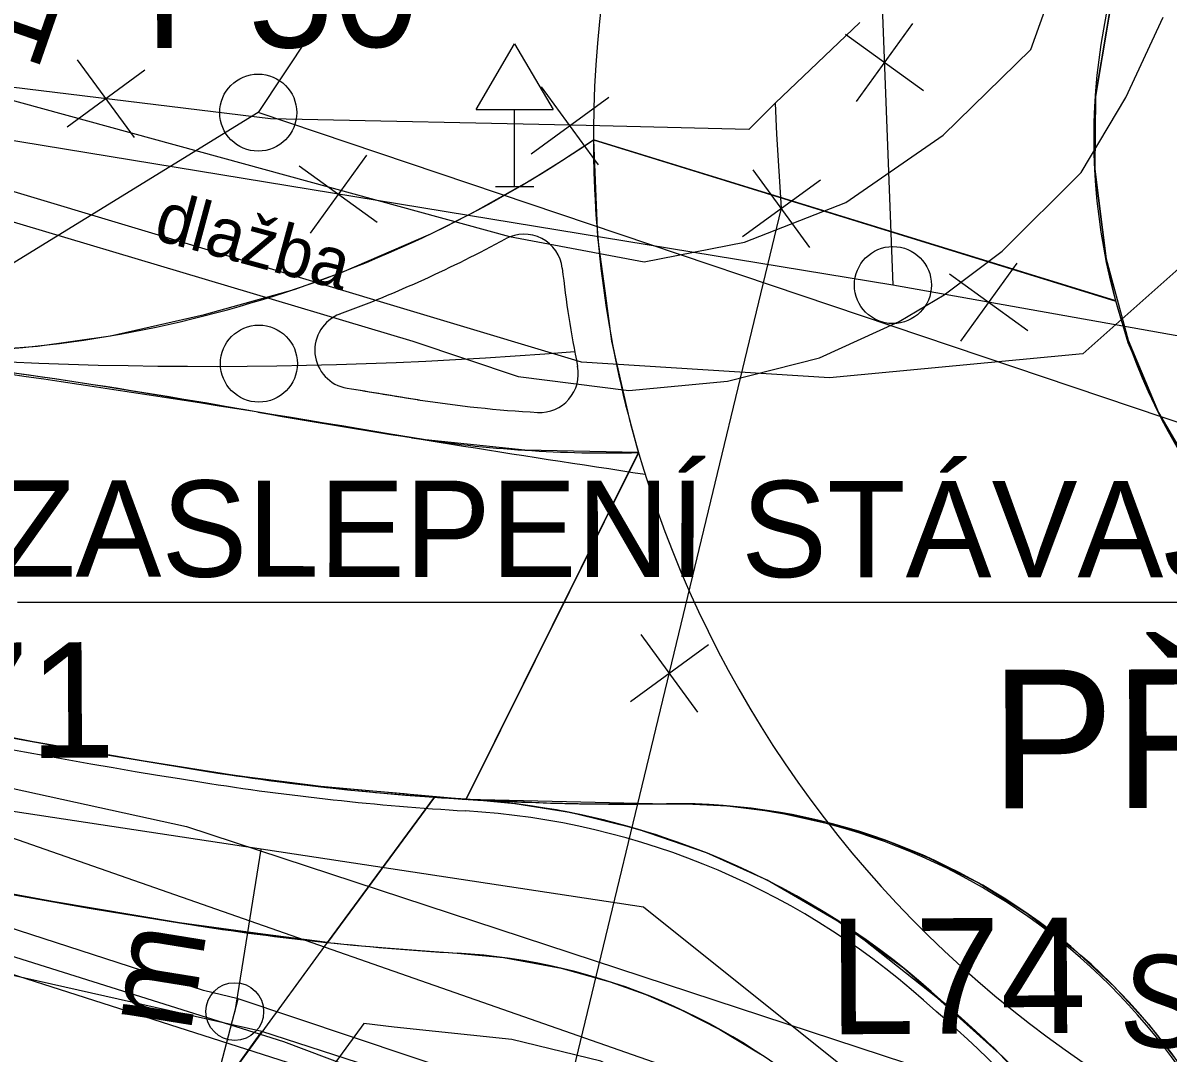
# Model space of a CAD drawing. Extents: x -643342 to -638635, y -1201752 to -1189948.
# Drawn here: x -639514.49 to -639499.63, y -1192725.54 to -1192712.17 of the extents above; entities that cross this region are included whole.
import ezdxf

# ---------------------------------------------------------------- set-up
doc = ezdxf.new("R2010")
doc.units = 0
for name, color, linetype in [('-zbytky_kruháče', 7, 'Continuous'), ('2', 7, 'Continuous'), ('IS_PLYN_STL', 7, 'Continuous'), ('IS_TELEF_MISTNI_ZAMERENO', 7, 'Continuous'), ('IS_VODOVOD_VAS', 7, 'Continuous'), ('K-HRANICE_KN', 7, 'Continuous'), ('kanalizace_dešťová_stávající', 7, 'Continuous'), ('N-CHODNIK', 7, 'Continuous'), ('N-KAN_DEST_SACHTY-NÁVRH', 7, 'Continuous'), ('N-KAN_DEST_TRASA-NÁVRH', 7, 'Continuous'), ('N-OBVOD STAVBY 06', 7, 'Continuous'), ('N-OSA', 7, 'Continuous'), ('N-rusene_vedeni', 7, 'Continuous'), ('N-SILNICE', 7, 'Continuous'), ('N-SRAFY_PLOCHY', 7, 'Continuous'), ('RWE_STL_PRIPOJKY', 7, 'Continuous'), ('RWE_STL_RADY', 7, 'Continuous'), ('tomaštík - Džuganovi - Vrstva 36', 7, 'Continuous'), ('Vrstva 46', 7, 'Continuous'), ('Z-hrany_a_čáry', 7, 'Continuous'), ('Z-popisy', 7, 'Continuous'), ('Z-značky', 7, 'Continuous'), ('Z-šachty_poklopy', 7, 'Continuous')]:
    doc.layers.add(name, color=color, linetype=linetype)

msp = doc.modelspace()

# ---------------------------------------------------------------- linework, layer by layer
at = {"layer": '-zbytky_kruháče'}
for centre, radius, start, end in [((-639492.588, -1192713.663), 14.5, 152.4602, 296.3322), ((-639516.023, -1192700.666), 15.789, 267.4282, 304.4652), ((-639526.387, -1192800.021), 84.137, 79.7689, 83.41017), ((-639465.318, -1192444.786), 276.313, 260.3906, 261.44619)]:
    msp.add_arc(centre, radius, start, end, dxfattribs=at)
at = {"layer": '2'}
msp.add_line((-639514.564, -1192719.686), (-639469.586, -1192719.686), dxfattribs=at)
msp.add_circle((-639511.743, -1192725.003), 0.375, dxfattribs=at)
at = {"layer": 'IS_PLYN_STL'}
for points in [[(-639501.39, -1192783.75), (-639500.989, -1192780.093), (-639500.16, -1192772.52), (-639499.45, -1192766.45), (-639499.2, -1192762.17), (-639498.55, -1192754.89), (-639497.68, -1192743.88), (-639497.18, -1192733.61), (-639497.87, -1192731.06), (-639499.7, -1192729.08), (-639500.91, -1192728.3), (-639501.94, -1192727.99), (-639507.97, -1192726.09), (-639511.7, -1192724.84), (-639512.15, -1192724.73), (-639515.02, -1192723.8), (-639520.31, -1192722.34), (-639520.46, -1192722.3), (-639520.92, -1192722.11)], [(-639512.5, -1192727.91), (-639512.25, -1192726.94), (-639511.7, -1192724.84)]]:
    msp.add_lwpolyline(points, dxfattribs=at)
at = {"layer": 'IS_TELEF_MISTNI_ZAMERENO'}
for p, q in [((-639503.63, -1192712.16), (-639504.73, -1192713.21)), ((-639511.28, -1192713.41), (-639515.55, -1192712.89)), ((-639504.73, -1192713.21), (-639505.07, -1192713.55)), ((-639504.73, -1192713.21), (-639504.71, -1192713.61)), ((-639507.18, -1192713.5), (-639511.28, -1192713.41)), ((-639505.07, -1192713.55), (-639507.18, -1192713.5)), ((-639504.71, -1192713.61), (-639504.65, -1192714.57)), ((-639504.65, -1192714.57), (-639507.56, -1192726.64)), ((-639504.65, -1192714.57), (-639507.56, -1192726.64)), ((-639515, -1192724.17), (-639511.11, -1192725.39)), ((-639515, -1192724.17), (-639511.11, -1192725.39)), ((-639511.11, -1192725.39), (-639509.95, -1192725.83))]:
    msp.add_line(p, q, dxfattribs=at)
at = {"layer": 'IS_VODOVOD_VAS'}
msp.add_lwpolyline([(-639496.09, -1192729.96), (-639496.274, -1192729.942), (-639497.14, -1192730.02), (-639497.319, -1192730.013), (-639497.98, -1192729.852), (-639517.2, -1192723.7), (-639533.16, -1192716.44), (-639534.26, -1192716.19), (-639547.57, -1192711.28), (-639564.69, -1192707.49), (-639577.32, -1192705.32), (-639579.08, -1192705.18), (-639581.13, -1192706.12), (-639584.92, -1192706.29)], dxfattribs=at)
at = {"layer": 'K-HRANICE_KN'}
for p, q in [((-639507.244, -1192716.571), (-639522.497, -1192711.992)), ((-639507.244, -1192716.571), (-639522.497, -1192711.992)), ((-639499.172, -1192715.073), (-639500.733, -1192716.465)), ((-639499.172, -1192715.073), (-639500.733, -1192716.465)), ((-639500.733, -1192716.465), (-639504.024, -1192716.775)), ((-639500.733, -1192716.465), (-639504.024, -1192716.775)), ((-639504.024, -1192716.775), (-639507.244, -1192716.571)), ((-639504.024, -1192716.775), (-639507.244, -1192716.571)), ((-639514.8, -1192722.07), (-639512.37, -1192722.6)), ((-639512.37, -1192722.6), (-639501.84, -1192726.06))]:
    msp.add_line(p, q, dxfattribs=at)
at = {"layer": 'kanalizace_dešťová_stávající'}
for p, q in [((-639504.48, -1192681.98), (-639503.2, -1192715.57)), ((-639503.2, -1192715.57), (-639578.69, -1192703.18)), ((-639487.73, -1192718.33), (-639503.2, -1192715.57))]:
    msp.add_line(p, q, dxfattribs=at)
at = {"layer": 'N-CHODNIK'}
msp.add_lwpolyline([(-639519.358, -1192722.513), (-639519.9, -1192724.87), (-639515.62, -1192725.85), (-639512.469, -1192726.756), (-639510.539, -1192724.105), (-639511.377, -1192723.998), (-639512.461, -1192723.852), (-639514.111, -1192723.576), (-639515.895, -1192723.247), (-639517.764, -1192722.866)], close=True, dxfattribs=at)
at = {"layer": 'N-KAN_DEST_SACHTY-NÁVRH'}
msp.add_circle((-639511.439, -1192713.331), 0.5, dxfattribs=at)
at = {"layer": 'N-KAN_DEST_TRASA-NÁVRH'}
for points in [[(-639583.962, -1192528.01), (-639550.452, -1192564.184), (-639529.583, -1192588.026), (-639514.491, -1192612.048), (-639507.737, -1192644.326), (-639498.832, -1192694.254), (-639511.439, -1192713.331), (-639516.613, -1192716.507), (-639553.938, -1192703.739), (-639570.485, -1192701.616), (-639578.687, -1192703.18)], [(-639355.755, -1192712.633), (-639405.298, -1192719.503), (-639444.905, -1192722.803), (-639490.998, -1192720.223), (-639511.439, -1192713.331)]]:
    msp.add_lwpolyline(points, dxfattribs=at)
at = {"layer": 'N-OBVOD STAVBY 06'}
for points in [[(-639510.069, -1192725.158), (-639511.446, -1192727.05), (-639512.469, -1192726.756), (-639515.316, -1192725.938), (-639515.62, -1192725.85), (-639519.9, -1192724.87), (-639520.863, -1192724.597), (-639520.555, -1192723.257)], [(-639502.579, -1192729.232), (-639503.805, -1192727.835), (-639505.37, -1192726.464), (-639506.99, -1192725.648), (-639508.145, -1192725.368), (-639509.676, -1192725.206), (-639510.069, -1192725.158)]]:
    msp.add_lwpolyline(points, dxfattribs=at)
at = {"layer": 'N-OSA'}
msp.add_arc((-639512.074, -1192658.483), 58.143, 250.31441, 274.68016, dxfattribs=at)
at = {"layer": 'N-rusene_vedeni'}
for p, q in [((-639502.944, -1192712.172), (-639503.676, -1192713.186)), ((-639503.817, -1192712.313), (-639502.803, -1192713.045)), ((-639512.91, -1192712.781), (-639513.92, -1192713.519)), ((-639513.046, -1192713.655), (-639513.784, -1192712.645)), ((-639507.023, -1192714.007), (-639507.76, -1192712.998)), ((-639506.887, -1192713.134), (-639507.896, -1192713.871)), ((-639510.034, -1192713.882), (-639510.765, -1192714.895)), ((-639510.906, -1192714.023), (-639509.893, -1192714.754)), ((-639504.276, -1192715.082), (-639505.014, -1192714.072)), ((-639504.14, -1192714.208), (-639505.15, -1192714.946)), ((-639501.591, -1192715.285), (-639502.322, -1192716.299)), ((-639502.463, -1192715.426), (-639501.45, -1192716.158)), ((-639505.731, -1192721.117), (-639506.469, -1192720.107)), ((-639505.595, -1192720.243), (-639506.605, -1192720.981))]:
    msp.add_line(p, q, dxfattribs=at)
at = {"layer": 'N-SILNICE'}
msp.add_line((-639510.539, -1192724.105), (-639509.151, -1192722.22), dxfattribs=at)
msp.add_circle((-639492.588, -1192713.663), 8, dxfattribs=at)
for centre, radius, start, end in [((-639516.023, -1192700.666), 16.289, 290.2787, 298.5882), ((-639507.989, -1192715.409), 0.5, 6.4672, 118.5882), ((-639492.588, -1192713.663), 15, 186.4672, 191.391), ((-639510.204, -1192716.415), 0.5, 110.2787, 260.6168), ((-639507.783, -1192716.724), 0.5, 266.7338, 11.391), ((-639453.766, -1192373.81), 347.722, 260.6455, 260.80232), ((-639506.892, -1192701.125), 16.125, 261.1699, 266.7338), ((-639496.485, -1192623.111), 100, 250.31486, 260.98854), ((-639496.485, -1192623.111), 100.15, 250.31486, 260.98854), ((-639506.892, -1192701.125), 16.625, 261.1699, 271.3474), ((-639496.485, -1192623.111), 102, 250.31486, 260.98854), ((-639506.666, -1192687.309), 35, 260.9885, 270.8671), ((-639506.666, -1192687.309), 35, 260.9885, 266.6063), ((-639506.666, -1192687.309), 35.15, 260.9885, 266.6063), ((-639509.33, -1192732.23), 10, 47.2487, 86.6063), ((-639509.33, -1192732.23), 9.85, 47.2487, 86.6063), ((-639506.015, -1192730.304), 8, 9.4731, 90.8671), ((-639506.666, -1192687.309), 37, 260.9885, 266.6063), ((-639509.33, -1192732.23), 8, 47.2487, 86.6063), ((-639512.285, -1192736.291), 15, 4.9967, 49.491), ((-639512.285, -1192736.291), 14.85, 4.9967, 49.491)]:
    msp.add_arc(centre, radius, start, end, dxfattribs=at)
at = {"layer": 'N-SRAFY_PLOCHY'}
for p, q in [((-639500.57, -1192713.12), (-639500.31, -1192711.571)), ((-639500.578, -1192714.067), (-639500.57, -1192713.12)), ((-639507.503, -1192713.959), (-639507.088, -1192713.684)), ((-639500.304, -1192715.777), (-639507.088, -1192713.684)), ((-639507.088, -1192713.684), (-639507.034, -1192714.953)), ((-639507.088, -1192713.684), (-639500.304, -1192715.778)), ((-639507.916, -1192714.215), (-639507.503, -1192713.959)), ((-639500.433, -1192715.231), (-639500.578, -1192714.067)), ((-639508.657, -1192714.632), (-639507.916, -1192714.215)), ((-639509.197, -1192714.904), (-639508.657, -1192714.632)), ((-639510.35, -1192715.401), (-639509.197, -1192714.904)), ((-639507.034, -1192714.953), (-639506.94, -1192715.647)), ((-639500.304, -1192715.778), (-639500.433, -1192715.231)), ((-639510.974, -1192715.627), (-639510.35, -1192715.401)), ((-639512.137, -1192715.953), (-639510.974, -1192715.627)), ((-639506.94, -1192715.647), (-639506.853, -1192716.297)), ((-639500.147, -1192716.322), (-639500.304, -1192715.777)), ((-639513.356, -1192716.229), (-639512.137, -1192715.953)), ((-639514.302, -1192716.362), (-639513.356, -1192716.229)), ((-639506.853, -1192716.297), (-639506.624, -1192717.302)), ((-639499.739, -1192717.249), (-639500.147, -1192716.322)), ((-639515.291, -1192716.439), (-639514.302, -1192716.362)), ((-639514.081, -1192716.789), (-639514.907, -1192716.671)), ((-639513.388, -1192716.894), (-639514.081, -1192716.789)), ((-639512.065, -1192717.112), (-639513.388, -1192716.894)), ((-639510.788, -1192717.332), (-639512.065, -1192717.112)), ((-639509.269, -1192717.581), (-639510.788, -1192717.332)), ((-639506.624, -1192717.302), (-639506.502, -1192717.747)), ((-639499.203, -1192718.201), (-639499.739, -1192717.249)), ((-639507.977, -1192717.714), (-639509.269, -1192717.581)), ((-639508.738, -1192722.247), (-639506.502, -1192717.745)), ((-639506.502, -1192717.747), (-639508.738, -1192722.247)), ((-639506.502, -1192717.745), (-639507.977, -1192717.714)), ((-639516.396, -1192721.108), (-639514.007, -1192721.564)), ((-639514.408, -1192721.491), (-639515.681, -1192721.245)), ((-639512.946, -1192721.747), (-639514.408, -1192721.491)), ((-639514.007, -1192721.564), (-639512.148, -1192721.877)), ((-639511.717, -1192721.942), (-639512.946, -1192721.747)), ((-639512.148, -1192721.877), (-639510.821, -1192722.061)), ((-639510.558, -1192722.091), (-639511.717, -1192721.942)), ((-639510.821, -1192722.061), (-639508.738, -1192722.247)), ((-639509.546, -1192722.175), (-639510.558, -1192722.091)), ((-639509.151, -1192722.22), (-639510.539, -1192724.105)), ((-639510.539, -1192724.105), (-639509.151, -1192722.22)), ((-639509.151, -1192722.22), (-639509.546, -1192722.175)), ((-639508.738, -1192722.247), (-639509.151, -1192722.22)), ((-639508.738, -1192722.247), (-639506.136, -1192722.305)), ((-639508.106, -1192722.305), (-639508.738, -1192722.247)), ((-639508.738, -1192722.247), (-639507.696, -1192722.293)), ((-639508.106, -1192722.305), (-639508.738, -1192722.247)), ((-639507.696, -1192722.293), (-639507.079, -1192722.306)), ((-639507.37, -1192722.423), (-639508.106, -1192722.305)), ((-639507.568, -1192722.386), (-639508.106, -1192722.305)), ((-639506.958, -1192722.515), (-639507.568, -1192722.386)), ((-639506.516, -1192722.634), (-639507.37, -1192722.423)), ((-639507.079, -1192722.306), (-639505.887, -1192722.305)), ((-639505.887, -1192722.305), (-639505.347, -1192722.332)), ((-639505.347, -1192722.332), (-639504.724, -1192722.408)), ((-639504.724, -1192722.408), (-639503.833, -1192722.607)), ((-639506.281, -1192722.706), (-639506.958, -1192722.515)), ((-639505.619, -1192722.943), (-639506.516, -1192722.634)), ((-639505.619, -1192722.943), (-639506.281, -1192722.706)), ((-639503.833, -1192722.607), (-639503.273, -1192722.788)), ((-639503.273, -1192722.788), (-639502.739, -1192723.005)), ((-639504.83, -1192723.299), (-639505.619, -1192722.943)), ((-639504.83, -1192723.299), (-639505.619, -1192722.943)), ((-639502.739, -1192723.005), (-639502.082, -1192723.337)), ((-639515.895, -1192723.247), (-639514.111, -1192723.576)), ((-639503.783, -1192723.909), (-639504.83, -1192723.299)), ((-639504.029, -1192723.75), (-639504.83, -1192723.299)), ((-639502.082, -1192723.337), (-639501.46, -1192723.727)), ((-639514.111, -1192723.576), (-639512.215, -1192723.89)), ((-639503.061, -1192724.438), (-639504.029, -1192723.75)), ((-639501.46, -1192723.727), (-639500.838, -1192724.204)), ((-639512.215, -1192723.89), (-639510.539, -1192724.105)), ((-639502.621, -1192724.829), (-639503.783, -1192723.909)), ((-639510.539, -1192724.105), (-639510.202, -1192724.139)), ((-639510.202, -1192724.139), (-639509.782, -1192724.177)), ((-639509.782, -1192724.177), (-639509.334, -1192724.212)), ((-639509.334, -1192724.212), (-639508.856, -1192724.244)), ((-639500.838, -1192724.204), (-639500.322, -1192724.683)), ((-639508.856, -1192724.244), (-639508.256, -1192724.302)), ((-639508.256, -1192724.302), (-639507.508, -1192724.44)), ((-639507.508, -1192724.44), (-639506.869, -1192724.617)), ((-639501.891, -1192725.476), (-639503.061, -1192724.438)), ((-639506.869, -1192724.617), (-639506.408, -1192724.782)), ((-639506.408, -1192724.782), (-639505.95, -1192724.979)), ((-639500.322, -1192724.683), (-639499.884, -1192725.165)), ((-639501.775, -1192725.588), (-639502.621, -1192724.829)), ((-639505.95, -1192724.979), (-639505.447, -1192725.235)), ((-639505.447, -1192725.235), (-639504.923, -1192725.552)), ((-639499.884, -1192725.165), (-639499.485, -1192725.682)), ((-639501.024, -1192726.382), (-639501.891, -1192725.476))]:
    msp.add_line(p, q, dxfattribs=at)
for points in [[(-639499.36, -1192709.404), (-639499.869, -1192710.347), (-639500.31, -1192711.571), (-639500.57, -1192713.12), (-639500.578, -1192714.067), (-639500.433, -1192715.231), (-639500.147, -1192716.285), (-639499.752, -1192717.224), (-639499.203, -1192718.163)], [(-639519.358, -1192722.513), (-639519.9, -1192724.87), (-639515.62, -1192725.85), (-639512.469, -1192726.756), (-639510.539, -1192724.105), (-639511.377, -1192723.998), (-639512.461, -1192723.852), (-639514.111, -1192723.576), (-639515.895, -1192723.247), (-639517.764, -1192722.866), (-639519.358, -1192722.513)]]:
    msp.add_lwpolyline(points, dxfattribs=at)
for centre, radius, start, end in [((-639516.023, -1192700.666), 15.789, 267.4282, 304.4652), ((-639516.023, -1192700.666), 15.789, 267.4282, 304.4652), ((-639492.588, -1192713.663), 14.5, 180.0839, 196.3512), ((-639492.588, -1192713.663), 14.5, 180.0839, 196.3512), ((-639516.023, -1192700.666), 16.289, 290.2787, 298.5882), ((-639507.989, -1192715.409), 0.5, 6.4672, 118.5882), ((-639492.588, -1192713.663), 15, 186.4672, 191.391), ((-639510.204, -1192716.415), 0.5, 110.2787, 260.6168), ((-639544.673, -1192923.833), 209.267, 80.30858, 82.32701), ((-639544.673, -1192923.833), 209.267, 80.30858, 82.32701), ((-639507.783, -1192716.724), 0.5, 266.7338, 11.391), ((-639434.973, -1192259.237), 463.826, 260.65532, 260.77024), ((-639506.892, -1192701.125), 16.125, 261.1699, 266.7338), ((-639506.892, -1192701.125), 16.625, 261.1699, 271.3474), ((-639506.892, -1192701.125), 16.625, 261.1699, 271.3474), ((-639506.088, -1192730.383), 8.079, 9.6799, 90.3442)]:
    msp.add_arc(centre, radius, start, end, dxfattribs=at)
at = {"layer": 'RWE_STL_PRIPOJKY'}
msp.add_line((-639511.404, -1192722.894), (-639511.743, -1192725.003), dxfattribs=at)
at = {"layer": 'RWE_STL_RADY'}
msp.add_lwpolyline([(-639456.391, -1192717.157), (-639456.89, -1192717.146), (-639457.119, -1192717.369), (-639466.356, -1192717.248), (-639466.499, -1192728.212), (-639484.493, -1192728.011), (-639503.164, -1192726.268), (-639506.439, -1192723.649), (-639519.474, -1192721.668)], dxfattribs=at)
at = {"layer": 'Z-hrany_a_čáry'}
for p, q in [((-639501.41, -1192712.51), (-639501.151, -1192711.787)), ((-639500.176, -1192713.136), (-639499.69, -1192712.09)), ((-639517.55, -1192712.37), (-639508.175, -1192714.938)), ((-639502.548, -1192713.625), (-639501.41, -1192712.51)), ((-639520.3, -1192713.05), (-639509.43, -1192716.3)), ((-639500.758, -1192714.107), (-639500.176, -1192713.136)), ((-639503.81, -1192714.498), (-639502.548, -1192713.625)), ((-639501.78, -1192715.13), (-639500.758, -1192714.107)), ((-639505.126, -1192715.012), (-639503.81, -1192714.498)), ((-639508.175, -1192714.938), (-639506.43, -1192715.27)), ((-639506.43, -1192715.27), (-639505.126, -1192715.012)), ((-639502.534, -1192715.696), (-639501.78, -1192715.13)), ((-639503.117, -1192716.045), (-639502.534, -1192715.696)), ((-639504.152, -1192716.515), (-639503.117, -1192716.045)), ((-639509.43, -1192716.3), (-639508.066, -1192716.758)), ((-639505.349, -1192716.818), (-639504.152, -1192716.515)), ((-639508.066, -1192716.758), (-639506.627, -1192716.94)), ((-639506.627, -1192716.94), (-639505.349, -1192716.818)), ((-639503.3, -1192726.71), (-639527.524, -1192718.244)), ((-639511.39, -1192725.26), (-639514.64, -1192724.53)), ((-639512.47, -1192726.76), (-639511.39, -1192725.26)), ((-639509.83, -1192725.77), (-639511.39, -1192725.26))]:
    msp.add_line(p, q, dxfattribs=at)
at = {"layer": 'Z-značky'}
for p, q in [((-639508.61, -1192713.29), (-639508.11, -1192712.44)), ((-639508.11, -1192712.44), (-639507.61, -1192713.29)), ((-639508.61, -1192713.29), (-639507.61, -1192713.29)), ((-639508.11, -1192714.29), (-639508.11, -1192713.29)), ((-639508.36, -1192714.29), (-639507.86, -1192714.29))]:
    msp.add_line(p, q, dxfattribs=at)
at = {"layer": 'Z-šachty_poklopy'}
for centre in [(-639503.2, -1192715.57), (-639511.43, -1192716.59)]:
    msp.add_circle(centre, 0.5, dxfattribs=at)

# ---------------------------------------------------------------- texts
at = {"layer": '2'}
msp.add_text('PŘELOŽKA 7 STL', height=1.8, rotation=0.0705, dxfattribs=at).set_placement((-639501.934, -1192722.364))
at = {"layer": 'RWE_STL_RADY'}
for s, rotation, p in [('STLPE 110 - 14,38 m', 70.8102, (-639517.48, -1192721.918)), ('PE 32 - 2,0 m', 80.812, (-639513.672, -1192733.655)), ('STLPE 110 - 75,71 m', 354.4856, (-639500.29, -1192725.414))]:
    msp.add_text(s, height=1.2, rotation=rotation, dxfattribs=at).set_placement(p)
at = {"layer": 'tomaštík - Džuganovi - Vrstva 36'}
msp.add_text('ZASLEPENÍ STÁVAJÍCÍHO PLYNOVODU PE 90', height=1.25, rotation=359.9647, dxfattribs=at).set_placement((-639514.831, -1192719.356))
at = {"layer": 'Vrstva 46'}
for s, p in [('P50', (-639512.913, -1192712.494)), ('L71', (-639516.638, -1192721.722)), ('L74', (-639504.031, -1192725.299))]:
    msp.add_text(s, height=1.5, rotation=0.301, dxfattribs=at).set_placement(p)
at = {"layer": 'Z-popisy'}
msp.add_text('dlažba', height=0.65, rotation=344.8385, dxfattribs=at).set_placement((-639512.817, -1192714.972))

doc.saveas('drawing.dxf')
